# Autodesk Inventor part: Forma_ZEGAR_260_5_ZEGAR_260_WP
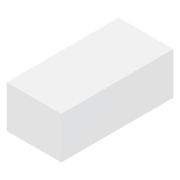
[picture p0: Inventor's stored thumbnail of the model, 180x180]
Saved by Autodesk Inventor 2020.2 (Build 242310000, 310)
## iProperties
Created: 2015-01
Part Number: Forma_ZEGAR_260_5_ZEGAR_260_WP
Material: Ogólny
Document SubType Name: Modeling
Designer: F.Stasiak
Density: 1 g/cm^3
Appearance: Domyślna
Catalog Web Link: www.expertbooks.pl
Manager: www.cadconsulting.pl
Company: Fabian Stasiak CAD Consulting
d0: -30.000 mm
d1: 39.000 mm
d2: 39.000 mm
d3: 80.000 mm
d4: 80.000 mm
d5: 60.000 mm
d6: 0.00 deg
Xmin: -39.000 mm
Ymin: -80.000 mm
Zmin: -30.000 mm
Xmax: 39.000 mm
Ymax: 80.000 mm
Zmax: 30.000 mm
Author: F.Stasiak
Subject: Zbiór ćwiczeń. Autodesk Inventor 2020. Kurs Professional
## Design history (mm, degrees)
sketch "Szkic1"
  geometry: L1 (-39, 80)-(39, 80); L2 (39, 80)-(39, -80); L3 (39, -80)-(-39, -80); L4 (-39, -80)-(-39, 80); 1 further point
  constraints: 8 end point, 2 parallel, 1 horizontal, 1 perpendicular, 1 other
  dimensions: "d1" = 39 distance from line of L4 point (0, 0) (= -Xmin); "d2" = 39 distance from line of L2 point (0, 0) (= Xmax); "d3" = 80 distance from line of L3 point (0, 0) (= -Ymin); "d4" = 80 distance from line of L1 point (0, 0) (= Ymax)
extrude "Wyciągnięcie proste1" join sketch "Szkic1" distance "d5" = 60 (= Zmax - Zmin); taper "d6" = 0 deg
node "Bryła1"
other parameters: "Xmin" = -39 [user parameter; used in 1 equation term], "Ymin" = -80 [user parameter; used in 1 equation term], "Zmin" = -30 [user parameter; used in 1 equation term], "Xmax" = 39 [user parameter; used in 1 equation term], "Ymax" = 80 [user parameter; used in 1 equation term], "Zmax" = 30 [user parameter; used in 1 equation term], "d0" = -30
